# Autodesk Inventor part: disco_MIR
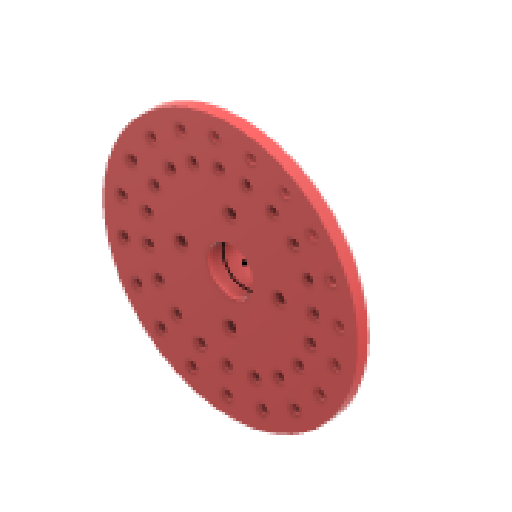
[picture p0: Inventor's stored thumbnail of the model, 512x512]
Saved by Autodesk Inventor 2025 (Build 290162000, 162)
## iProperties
Created: 2025-03
Part Number: disco_MIR
Material: Plastica ABS
Document SubType Name: Modeling
Designer: R5800u
Density: 1.06 g/cm^3
Appearance: Liscia - Rosso
Author: R5800u
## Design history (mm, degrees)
derived "disco.ipt"
  sketch "Schizzo1"
    geometry: C1 r 70 at (0, 0); C2 r 12.5 at (0, 0); 1 further point
    constraints: 2 centre point
  sketch "Schizzo2"
    geometry: C1 r 3 at (-1.5, -60); C2 r 3 at (-1.5, -46); 1 further point
    constraints: 2 centre point
  sketch "Schizzo3"
    geometry: C1 r 12.5 at (0, 0); C2 r 25 at (0, 0); 1 further point
    constraints: 2 centre point
chamfer "Smusso1" distance "d1" = 2; stored, may be unused: second distance "d2" = 2, angle "d3" = 45 deg
sketch "Schizzo4"
  geometry: C1 r 25 at (0, 0); C2 r 12.5 at (0, 0) reference; 1 further point
  constraints: 1 centre point, 1 coincident
  dimensions: "d4" = 50 diameter of C1
extrude "Estrusione1" join sketch "Schizzo4" distance "d5" = 25; taper "d6" = 0 deg
fillet "Raccordo1" dims "d7" = 5
node "Scanalatura1"
sketch "Schizzo5"
  geometry: C1 r 3.2 at (27, 0) reference; C2 r 3.2 at (0, 27) reference; C3 r 3.2 at (-27, 0) reference; C4 r 3.2 at (0, -27) reference; C5 r 12.5 at (0, 0) reference; 1 further point
hole "Foro1" sketch "Schizzo5" at (27, 0), (0, -27), (-27, 0), (0, 27) diameter "d8" = 6.4; stored, may be unused: countersink angle "d12" = 90 deg, drill point angle "d14" = 118 deg; dims "d9" = 6, "d10" = 12.6, "d11" = 2, "d13" = 8
sketch "Schizzo6"
  geometry: C1 r 18 at (0, 0); C2 r 12.5 at (0, 0) reference; 1 further point
  constraints: 1 centre point, 1 coincident
  dimensions: "d15" = 36 diameter of C1
extrude "Estrusione2" join sketch "Schizzo6" distance "d16" = 20; taper "d17" = 0 deg
fillet "Raccordo2" dims "d18" = 2
feature "Solido1::disco.ipt" dims "d0" = 10
tag "Lavorazione contrassegno1"
feature "Sede chiavetta mozzo"
node "Riferimento1"
node "Riferimento2"
node "Riferimento3"
node "Riferimento4"
node "Riferimento5"
node "Riferimento6"
node "Solido1"
